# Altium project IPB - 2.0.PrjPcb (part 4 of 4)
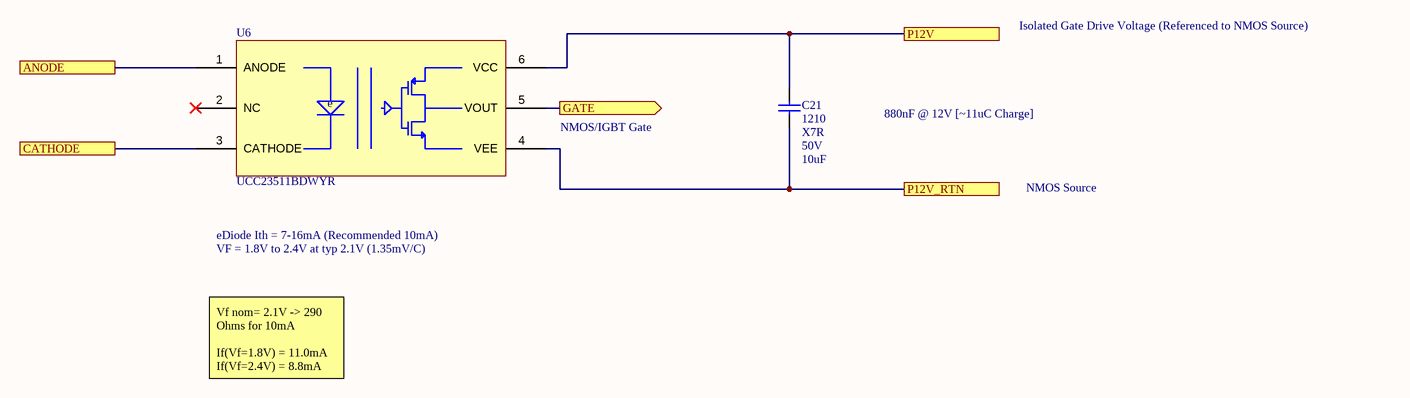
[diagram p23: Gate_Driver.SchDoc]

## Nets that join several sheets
COIL_DRV_HIGH: Local_Power_Supplies (Q1.2), 24V_to_12V_DCDC (C55.2 L4.1 R85.2), 24V_to_5V_DCDC (C45.2 L2.1 R81.2), Designator/Interface Channel A (K1_A.2 K2_A.2), Designator/Interface Channel A/Contactor Driver (D4_A.1), Designator/Interface Channel A/Contactor Driver (D4_B.1), Designator/Interface Channel A/Solid State Switches/Isolated Gate Drive Power - HIGH (C16_A.1 C17_A.2 C18_A.2 PS1_A.2), Designator/Interface Channel B (K1_B.2 K2_B.2), Designator/Interface Channel B/Contactor Driver (D4_C.1), Designator/Interface Channel B/Contactor Driver (D4_D.1), Designator/Interface Channel B/Solid State Switches/Isolated Gate Drive Power - HIGH (C16_B.1 C17_B.2 C18_B.2 PS1_B.2), Designator/Interface Channel C (K1_C.2 K2_C.2), Designator/Interface Channel C/Contactor Driver (D4_E.1), Designator/Interface Channel C/Contactor Driver (D4_F.1), Designator/Interface Channel C/Solid State Switches/Isolated Gate Drive Power - HIGH (C16_C.1 C17_C.2 C18_C.2 PS1_C.2), Designator/Interface Channel D (K1_D.2 K2_D.2), Designator/Interface Channel D/Contactor Driver (D4_G.1), Designator/Interface Channel D/Contactor Driver (D4_H.1), Designator/Interface Channel D/Solid State Switches/Isolated Gate Drive Power - HIGH (C16_D.1 C17_D.2 C18_D.2 PS1_D.2)
HV_P5V: Designator/Interface Channel A/Solid State Switches (C61_A.2 U22_A.5), Designator/Interface Channel A/Solid State Switches/Isolated Gate Drive Power - HIGH (C47_A.2 U15_A.3), Designator/Interface Channel A/Solid State Switches/Short Circuit Current Sense (5 pins), Designator/Interface Channel A/Solid State Switches/Short Circuit Logic Intergration (C51_A.2 Q5_A.2 U21_A.5)
HV_P5V: Designator/Interface Channel B/Solid State Switches (C61_B.2 U22_B.5), Designator/Interface Channel B/Solid State Switches/Isolated Gate Drive Power - HIGH (C47_B.2 U15_B.3), Designator/Interface Channel B/Solid State Switches/Short Circuit Current Sense (5 pins), Designator/Interface Channel B/Solid State Switches/Short Circuit Logic Intergration (C51_B.2 Q5_B.2 U21_B.5)
HV_P5V: Designator/Interface Channel C/Solid State Switches (C61_C.2 U22_C.5), Designator/Interface Channel C/Solid State Switches/Isolated Gate Drive Power - HIGH (C47_C.2 U15_C.3), Designator/Interface Channel C/Solid State Switches/Short Circuit Current Sense (5 pins), Designator/Interface Channel C/Solid State Switches/Short Circuit Logic Intergration (C51_C.2 Q5_C.2 U21_C.5)
HV_P5V: Designator/Interface Channel D/Solid State Switches (C61_D.2 U22_D.5), Designator/Interface Channel D/Solid State Switches/Isolated Gate Drive Power - HIGH (C47_D.2 U15_D.3), Designator/Interface Channel D/Solid State Switches/Short Circuit Current Sense (5 pins), Designator/Interface Channel D/Solid State Switches/Short Circuit Logic Intergration (C51_D.2 Q5_D.2 U21_D.5)
HV_P12V: Designator/Interface Channel A/Solid State Switches/Isolated Gate Drive Power - HIGH (6 pins), Designator/Interface Channel A/Solid State Switches/Short Circuit Logic Intergration/MOSFET HIGH Driver (C21_A.2 U6_A.6)
HV_P12V: Designator/Interface Channel B/Solid State Switches/Isolated Gate Drive Power - HIGH (6 pins), Designator/Interface Channel B/Solid State Switches/Short Circuit Logic Intergration/MOSFET HIGH Driver (C21_B.2 U6_B.6)
HV_P12V: Designator/Interface Channel C/Solid State Switches/Isolated Gate Drive Power - HIGH (6 pins), Designator/Interface Channel C/Solid State Switches/Short Circuit Logic Intergration/MOSFET HIGH Driver (C21_C.2 U6_C.6)
HV_P12V: Designator/Interface Channel D/Solid State Switches/Isolated Gate Drive Power - HIGH (6 pins), Designator/Interface Channel D/Solid State Switches/Short Circuit Logic Intergration/MOSFET HIGH Driver (C21_D.2 U6_D.6)
ISO_RTN_Solid State Switches: Designator/Interface Channel A/Solid State Switches (8 pins), Designator/Interface Channel A/Solid State Switches/Isolated Gate Drive Power - HIGH (8 pins), Designator/Interface Channel A/Solid State Switches/Short Circuit Current Sense (8 pins), Designator/Interface Channel A/Solid State Switches/Short Circuit Logic Intergration (5 pins), Designator/Interface Channel A/Solid State Switches/Short Circuit Logic Intergration/MOSFET HIGH Driver (C21_A.1 U6_A.3 U6_A.4)
ISO_RTN_Solid State Switches: Designator/Interface Channel B/Solid State Switches (8 pins), Designator/Interface Channel B/Solid State Switches/Isolated Gate Drive Power - HIGH (8 pins), Designator/Interface Channel B/Solid State Switches/Short Circuit Current Sense (8 pins), Designator/Interface Channel B/Solid State Switches/Short Circuit Logic Intergration (5 pins), Designator/Interface Channel B/Solid State Switches/Short Circuit Logic Intergration/MOSFET HIGH Driver (C21_B.1 U6_B.3 U6_B.4)
ISO_RTN_Solid State Switches: Designator/Interface Channel C/Solid State Switches (8 pins), Designator/Interface Channel C/Solid State Switches/Isolated Gate Drive Power - HIGH (8 pins), Designator/Interface Channel C/Solid State Switches/Short Circuit Current Sense (8 pins), Designator/Interface Channel C/Solid State Switches/Short Circuit Logic Intergration (5 pins), Designator/Interface Channel C/Solid State Switches/Short Circuit Logic Intergration/MOSFET HIGH Driver (C21_C.1 U6_C.3 U6_C.4)
ISO_RTN_Solid State Switches: Designator/Interface Channel D/Solid State Switches (8 pins), Designator/Interface Channel D/Solid State Switches/Isolated Gate Drive Power - HIGH (8 pins), Designator/Interface Channel D/Solid State Switches/Short Circuit Current Sense (8 pins), Designator/Interface Channel D/Solid State Switches/Short Circuit Logic Intergration (5 pins), Designator/Interface Channel D/Solid State Switches/Short Circuit Logic Intergration/MOSFET HIGH Driver (C21_D.1 U6_D.3 U6_D.4)
LV_GND: Top (5 pins), Input_Current_Limit (8 pins), Input Current Limit/Current Sense (C10_A.2 U4_A.5 U4_A.6), Input Current Limit/Current Limit - Configurable (8 pins), Input Current Limit/12V to 5V (Linear) - ISNS Power (C57_A.1 C58_A.1 R88_A.1 U20_A.4), Input Current Limit/Channel Logic (18 pins), Mezzanine_Conn (33 pins), Fault_Sensing (C11.2 C12.1 U5.7 U5.8), Local_Power_Supplies (C14.2 C15.2 R60.1), 24V_to_12V_DCDC (6 pins), 24V_to_5V_DCDC (6 pins), Designator/Interface Channel A (7 pins), Designator/Interface Channel A/Overcurrent Current Sense (C10_B.2 U4_B.5 U4_B.6), Designator/Interface Channel A/Channel Logic (18 pins), Designator/Interface Channel A/Current Limit - Configurable (8 pins), Designator/Interface Channel A/Contactor Driver (Q2_A.3 R65_A.1), Designator/Interface Channel A/Contactor Driver (Q2_B.3 R65_B.1), Designator/Interface Channel A/Anti-Alias Filter (5 pins), Designator/Interface Channel A/12V to 5V (Linear) - ISNS Power (C57_B.1 C58_B.1 R88_B.1 U20_B.4), Designator/Interface Channel A/Solid State Switches (Q4_A.2 Q8_A.3), Designator/Interface Channel A/Solid State Switches/Isolated Gate Drive Power - HIGH (C17_A.1 C18_A.1 C20_A.1 PS1_A.1), Designator/Interface Channel B (7 pins), Designator/Interface Channel B/Overcurrent Current Sense (C10_C.2 U4_C.5 U4_C.6), Designator/Interface Channel B/Channel Logic (18 pins), Designator/Interface Channel B/Current Limit - Configurable (8 pins), Designator/Interface Channel B/Contactor Driver (Q2_C.3 R65_C.1), Designator/Interface Channel B/Contactor Driver (Q2_D.3 R65_D.1), Designator/Interface Channel B/Anti-Alias Filter (5 pins), Designator/Interface Channel B/12V to 5V (Linear) - ISNS Power (C57_C.1 C58_C.1 R88_C.1 U20_C.4), Designator/Interface Channel B/Solid State Switches (Q4_B.2 Q8_B.3), Designator/Interface Channel B/Solid State Switches/Isolated Gate Drive Power - HIGH (C17_B.1 C18_B.1 C20_B.1 PS1_B.1), Designator/Interface Channel C (7 pins), Designator/Interface Channel C/Overcurrent Current Sense (C10_D.2 U4_D.5 U4_D.6), Designator/Interface Channel C/Channel Logic (18 pins), Designator/Interface Channel C/Current Limit - Configurable (8 pins), Designator/Interface Channel C/Contactor Driver (Q2_E.3 R65_E.1), Designator/Interface Channel C/Contactor Driver (Q2_F.3 R65_F.1), Designator/Interface Channel C/Anti-Alias Filter (5 pins), Designator/Interface Channel C/12V to 5V (Linear) - ISNS Power (C57_D.1 C58_D.1 R88_D.1 U20_D.4), Designator/Interface Channel C/Solid State Switches (Q4_C.2 Q8_C.3), Designator/Interface Channel C/Solid State Switches/Isolated Gate Drive Power - HIGH (C17_C.1 C18_C.1 C20_C.1 PS1_C.1), Designator/Interface Channel D (7 pins), Designator/Interface Channel D/Overcurrent Current Sense (C10_E.2 U4_E.5 U4_E.6), Designator/Interface Channel D/Channel Logic (18 pins), Designator/Interface Channel D/Current Limit - Configurable (8 pins), Designator/Interface Channel D/Contactor Driver (Q2_G.3 R65_G.1), Designator/Interface Channel D/Contactor Driver (Q2_H.3 R65_H.1), Designator/Interface Channel D/Anti-Alias Filter (5 pins), Designator/Interface Channel D/12V to 5V (Linear) - ISNS Power (C57_E.1 C58_E.1 R88_E.1 U20_E.4), Designator/Interface Channel D/Solid State Switches (Q4_D.2 Q8_D.3), Designator/Interface Channel D/Solid State Switches/Isolated Gate Drive Power - HIGH (C17_D.1 C18_D.1 C20_D.1 PS1_D.1)
LV_IGB_P24V: Mezzanine_Conn (5 pins), Local_Power_Supplies (D2.1)
LV_ISNS_P5V: Input_Current_Limit (5 pins), Input Current Limit/Current Sense (C10_A.1 U4_A.8), Input Current Limit/12V to 5V (Linear) - ISNS Power (C58_A.2 R87_A.2 U20_A.6)
LV_ISNS_P12V: Input Current Limit/12V to 5V (Linear) - ISNS Power (C57_A.2 U20_A.2), Local_Power_Supplies (C14.1 L1.2 R59.2), Designator/Interface Channel A/12V to 5V (Linear) - ISNS Power (C57_B.2 U20_B.2), Designator/Interface Channel B/12V to 5V (Linear) - ISNS Power (C57_C.2 U20_C.2), Designator/Interface Channel C/12V to 5V (Linear) - ISNS Power (C57_D.2 U20_D.2), Designator/Interface Channel D/12V to 5V (Linear) - ISNS Power (C57_E.2 U20_E.2)
LV_P5V: Top (U1.2), Input_Current_Limit (R42.2), Input Current Limit/Current Limit - Configurable (5 pins), Input Current Limit/Channel Logic (15 pins), Fault_Sensing (C11.1 C12.2 U5.16), 24V_to_5V_DCDC (C42.1 U17.3), Designator/Interface Channel A (5 pins), Designator/Interface Channel A/Channel Logic (15 pins), Designator/Interface Channel A/Current Limit - Configurable (5 pins), Designator/Interface Channel A/Anti-Alias Filter (C36_A.1 C37_A.2 U16_A.8), Designator/Interface Channel B (5 pins), Designator/Interface Channel B/Channel Logic (15 pins), Designator/Interface Channel B/Current Limit - Configurable (5 pins), Designator/Interface Channel B/Anti-Alias Filter (C36_B.1 C37_B.2 U16_B.8), Designator/Interface Channel C (5 pins), Designator/Interface Channel C/Channel Logic (15 pins), Designator/Interface Channel C/Current Limit - Configurable (5 pins), Designator/Interface Channel C/Anti-Alias Filter (C36_C.1 C37_C.2 U16_C.8), Designator/Interface Channel D (5 pins), Designator/Interface Channel D/Channel Logic (15 pins), Designator/Interface Channel D/Current Limit - Configurable (5 pins), Designator/Interface Channel D/Anti-Alias Filter (C36_D.1 C37_D.2 U16_D.8)
LV_P12V: Local_Power_Supplies (L1.1), 24V_to_12V_DCDC (C52.1 U19.3)
N187: IGB_Power_Conn (J1.B), Designator/Interface Channel A (K2_A.1 R103_A.1), Designator/Interface Channel B (K2_B.1 R103_B.1), Designator/Interface Channel C (K2_C.1 R103_C.1), Designator/Interface Channel D (K2_D.1 R103_D.1)
ACTIVE-FAULT: Input_Current_Limit (R41.1 TP1.1), Input Current Limit/Channel Logic (R71_A.2 U11_A.1)
ACTIVE-FAULT: Designator/Interface Channel A/Channel Logic (R71_B.2 U11_B.1), Designator/Interface Channel A/Current Limit - Configurable (U8_B.4)
ACTIVE-FAULT: Designator/Interface Channel B/Channel Logic (R71_C.2 U11_C.1), Designator/Interface Channel B/Current Limit - Configurable (U8_C.4)
ACTIVE-FAULT: Designator/Interface Channel C/Channel Logic (R71_D.2 U11_D.1), Designator/Interface Channel C/Current Limit - Configurable (U8_D.4)
ACTIVE-FAULT: Designator/Interface Channel D/Channel Logic (R71_E.2 U11_E.1), Designator/Interface Channel D/Current Limit - Configurable (U8_E.4)
BOARD_TEMP: Top (C1.2 R1.1), Mezzanine_Conn (R33.1 R36.1)
CH-EN_Solid State Switches: Designator/Interface Channel A/Solid State Switches (Q4_A.4), Designator/Interface Channel A/Solid State Switches/Short Circuit Logic Intergration (R92_A.1)
CH-EN_Solid State Switches: Designator/Interface Channel B/Solid State Switches (Q4_B.4), Designator/Interface Channel B/Solid State Switches/Short Circuit Logic Intergration (R92_B.1)
CH-EN_Solid State Switches: Designator/Interface Channel C/Solid State Switches (Q4_C.4), Designator/Interface Channel C/Solid State Switches/Short Circuit Logic Intergration (R92_C.1)
CH-EN_Solid State Switches: Designator/Interface Channel D/Solid State Switches (Q4_D.4), Designator/Interface Channel D/Solid State Switches/Short Circuit Logic Intergration (R92_D.1)
CH-ENABLE: Input_Current_Limit (C2.2 R42.1), Input Current Limit/Channel Logic (R73_A.2 U10_A.3)
CH-I_Interface Channel A: Designator/Interface Channel A/Overcurrent Current Sense (U4_B.7), Designator/Interface Channel A/Current Limit - Configurable (R69_B.1), Designator/Interface Channel A/Anti-Alias Filter (R79_A.1)
CH-I_Interface Channel B: Designator/Interface Channel B/Overcurrent Current Sense (U4_C.7), Designator/Interface Channel B/Current Limit - Configurable (R69_C.1), Designator/Interface Channel B/Anti-Alias Filter (R79_B.1)
CH-I_Interface Channel C: Designator/Interface Channel C/Overcurrent Current Sense (U4_D.7), Designator/Interface Channel C/Current Limit - Configurable (R69_D.1), Designator/Interface Channel C/Anti-Alias Filter (R79_C.1)
CH-I_Interface Channel D: Designator/Interface Channel D/Overcurrent Current Sense (U4_E.7), Designator/Interface Channel D/Current Limit - Configurable (R69_E.1), Designator/Interface Channel D/Anti-Alias Filter (R79_D.1)
CHA_CURRENT_SET: Mezzanine_Conn (R4.1 R6.1), Designator/Interface Channel A/Current Limit - Configurable (R66_B.1)
CHA_FET_EN: Mezzanine_Conn (R19.1 R21.1), Designator/Interface Channel A/Channel Logic (R73_B.2 U10_B.3)
CHA_I: Mezzanine_Conn (R20.1 R22.1), Designator/Interface Channel A/Anti-Alias Filter (C38_A.1 U16_A.6 U16_A.7)
CHA_RLY_EN: Mezzanine_Conn (R3.1 R5.1), Designator/Interface Channel A/Contactor Driver (R64_A.1), Designator/Interface Channel A/Contactor Driver (R64_B.1)
CHB_CURRENT_SET: Mezzanine_Conn (R8.1 R10.1), Designator/Interface Channel B/Current Limit - Configurable (R66_C.1)
CHB_FET_EN: Mezzanine_Conn (R23.1 R25.1), Designator/Interface Channel B/Channel Logic (R73_C.2 U10_C.3)
CHB_I: Mezzanine_Conn (R24.1 R26.1), Designator/Interface Channel B/Anti-Alias Filter (C38_B.1 U16_B.6 U16_B.7)
CHB_RLY_EN: Mezzanine_Conn (R7.1 R9.1), Designator/Interface Channel B/Contactor Driver (R64_C.1), Designator/Interface Channel B/Contactor Driver (R64_D.1)
CHC_CURRENT_SET: Mezzanine_Conn (R12.1 R14.1), Designator/Interface Channel C/Current Limit - Configurable (R66_D.1)
CHC_FET_EN: Mezzanine_Conn (R27.1 R29.1), Designator/Interface Channel C/Channel Logic (R73_D.2 U10_D.3)
CHC_I: Mezzanine_Conn (R28.1 R30.1), Designator/Interface Channel C/Anti-Alias Filter (C38_C.1 U16_C.6 U16_C.7)
CHC_RLY_EN: Mezzanine_Conn (R11.1 R13.1), Designator/Interface Channel C/Contactor Driver (R64_E.1), Designator/Interface Channel C/Contactor Driver (R64_F.1)
CHD_CURRENT_SET: Mezzanine_Conn (R16.1 R18.1), Designator/Interface Channel D/Current Limit - Configurable (R66_E.1)
CHD_FET_EN: Mezzanine_Conn (R31.1 R34.1), Designator/Interface Channel D/Channel Logic (R73_E.2 U10_E.3)
CHD_I: Mezzanine_Conn (R32.1 R35.1), Designator/Interface Channel D/Anti-Alias Filter (C38_D.1 U16_D.6 U16_D.7)
CHD_RLY_EN: Mezzanine_Conn (R15.1 R17.1), Designator/Interface Channel D/Contactor Driver (R64_G.1), Designator/Interface Channel D/Contactor Driver (R64_H.1)
COIL_RTN_HIGH_Interface Channel A: Designator/Interface Channel A (K1_A.5), Designator/Interface Channel A/Contactor Driver (D4_A.2 Q2_A.2)
COIL_RTN_HIGH_Interface Channel B: Designator/Interface Channel B (K1_B.5), Designator/Interface Channel B/Contactor Driver (D4_C.2 Q2_C.2)
COIL_RTN_HIGH_Interface Channel C: Designator/Interface Channel C (K1_C.5), Designator/Interface Channel C/Contactor Driver (D4_E.2 Q2_E.2)
COIL_RTN_HIGH_Interface Channel D: Designator/Interface Channel D (K1_D.5), Designator/Interface Channel D/Contactor Driver (D4_G.2 Q2_G.2)
COIL_RTN_LOW_Interface Channel A: Designator/Interface Channel A (K2_A.5), Designator/Interface Channel A/Contactor Driver (D4_B.2 Q2_B.2)
COIL_RTN_LOW_Interface Channel B: Designator/Interface Channel B (K2_B.5), Designator/Interface Channel B/Contactor Driver (D4_D.2 Q2_D.2)
COIL_RTN_LOW_Interface Channel C: Designator/Interface Channel C (K2_C.5), Designator/Interface Channel C/Contactor Driver (D4_F.2 Q2_F.2)
COIL_RTN_LOW_Interface Channel D: Designator/Interface Channel D (K2_D.5), Designator/Interface Channel D/Contactor Driver (D4_H.2 Q2_H.2)
FAULT-BUF_Solid State Switches: Designator/Interface Channel A/Solid State Switches (R83_A.2 TP5_A.1 U22_A.4), Designator/Interface Channel A/Solid State Switches/Short Circuit Logic Intergration (Q6_A.1 R90_A.2)
FAULT-BUF_Solid State Switches: Designator/Interface Channel B/Solid State Switches (R83_B.2 TP5_B.1 U22_B.4), Designator/Interface Channel B/Solid State Switches/Short Circuit Logic Intergration (Q6_B.1 R90_B.2)
FAULT-BUF_Solid State Switches: Designator/Interface Channel C/Solid State Switches (R83_C.2 TP5_C.1 U22_C.4), Designator/Interface Channel C/Solid State Switches/Short Circuit Logic Intergration (Q6_C.1 R90_C.2)
FAULT-BUF_Solid State Switches: Designator/Interface Channel D/Solid State Switches (R83_D.2 TP5_D.1 U22_D.4), Designator/Interface Channel D/Solid State Switches/Short Circuit Logic Intergration (Q6_D.1 R90_D.2)
FAULT-INJECT_Interface Channel A: Designator/Interface Channel A/Current Limit - Configurable (C24_B.1 R66_B.2 U7_B.2), Designator/Interface Channel A/Solid State Switches (Q8_A.4)
FAULT-INJECT_Interface Channel B: Designator/Interface Channel B/Current Limit - Configurable (C24_C.1 R66_C.2 U7_C.2), Designator/Interface Channel B/Solid State Switches (Q8_B.4)
FAULT-INJECT_Interface Channel C: Designator/Interface Channel C/Current Limit - Configurable (C24_D.1 R66_D.2 U7_D.2), Designator/Interface Channel C/Solid State Switches (Q8_C.4)
FAULT-INJECT_Interface Channel D: Designator/Interface Channel D/Current Limit - Configurable (C24_E.1 R66_E.2 U7_E.2), Designator/Interface Channel D/Solid State Switches (Q8_D.4)
FAULT_MUX_A: Mezzanine_Conn (J3.58), Fault_Sensing (U5.11)
FAULT_MUX_B: Mezzanine_Conn (J3.60), Fault_Sensing (U5.10)
FAULT_MUX_C: Mezzanine_Conn (J3.62), Fault_Sensing (U5.9)
FAULT_SENSE: Mezzanine_Conn (R39.1 R40.1), Fault_Sensing (U5.5)
FAULT_SENSE_IN0: Input Current Limit/Channel Logic (U11_A.4 U12_A.1 U14_A.6), Fault_Sensing (U5.4), Designator/Interface Channel A/Channel Logic (R70_B.2 U9_B.3), Designator/Interface Channel B/Channel Logic (R70_C.2 U9_C.3), Designator/Interface Channel C/Channel Logic (R70_D.2 U9_D.3), Designator/Interface Channel D/Channel Logic (R70_E.2 U9_E.3)
FAULT_SENSE_IN1: Fault_Sensing (U5.3), Designator/Interface Channel A/Channel Logic (U11_B.4 U12_B.1 U14_B.6)
FAULT_SENSE_IN2: Fault_Sensing (U5.2), Designator/Interface Channel B/Channel Logic (U11_C.4 U12_C.1 U14_C.6)
FAULT_SENSE_IN3: Fault_Sensing (U5.1), Designator/Interface Channel C/Channel Logic (U11_D.4 U12_D.1 U14_D.6)
FAULT_SENSE_IN4: Fault_Sensing (U5.15), Designator/Interface Channel D/Channel Logic (U11_E.4 U12_E.1 U14_E.6)
FAULT_SENSE_IN5: Top (R97.2), Fault_Sensing (U5.14)
FAULT_SENSE_IN6: Top (R96.2), Fault_Sensing (U5.13)
FAULT_SENSE_IN7: Top (R95.2), Fault_Sensing (U5.12)
GATE_DRV_HIGH_Solid State Switches: Designator/Interface Channel A/Solid State Switches (D7_A.2 R91_A.1), Designator/Interface Channel A/Solid State Switches/Short Circuit Logic Intergration/MOSFET HIGH Driver (U6_A.5)
GATE_DRV_HIGH_Solid State Switches: Designator/Interface Channel B/Solid State Switches (D7_B.2 R91_B.1), Designator/Interface Channel B/Solid State Switches/Short Circuit Logic Intergration/MOSFET HIGH Driver (U6_B.5)
GATE_DRV_HIGH_Solid State Switches: Designator/Interface Channel C/Solid State Switches (D7_C.2 R91_C.1), Designator/Interface Channel C/Solid State Switches/Short Circuit Logic Intergration/MOSFET HIGH Driver (U6_C.5)
GATE_DRV_HIGH_Solid State Switches: Designator/Interface Channel D/Solid State Switches (D7_D.2 R91_D.1), Designator/Interface Channel D/Solid State Switches/Short Circuit Logic Intergration/MOSFET HIGH Driver (U6_D.5)
INPUT-FAULT-RESET: Input Current Limit/Channel Logic (R74_A.2 U14_A.1), Mezzanine_Conn (R37.1 R38.1)
NetC10_B_1: Designator/Interface Channel A/Overcurrent Current Sense (C10_B.1 U4_B.8), Designator/Interface Channel A/12V to 5V (Linear) - ISNS Power (C58_B.2 R87_B.2 U20_B.6)
NetC10_C_1: Designator/Interface Channel B/Overcurrent Current Sense (C10_C.1 U4_C.8), Designator/Interface Channel B/12V to 5V (Linear) - ISNS Power (C58_C.2 R87_C.2 U20_C.6)
NetC10_D_1: Designator/Interface Channel C/Overcurrent Current Sense (C10_D.1 U4_D.8), Designator/Interface Channel C/12V to 5V (Linear) - ISNS Power (C58_D.2 R87_D.2 U20_D.6)
NetC10_E_1: Designator/Interface Channel D/Overcurrent Current Sense (C10_E.1 U4_E.8), Designator/Interface Channel D/12V to 5V (Linear) - ISNS Power (C58_E.2 R87_E.2 U20_E.6)
NetC59_A_1: Designator/Interface Channel A/Overcurrent Current Sense (U4_B.3 U4_B.4), Designator/Interface Channel A/Solid State Switches (C59_A.1 Q3_A.D)
NetC59_B_1: Designator/Interface Channel B/Overcurrent Current Sense (U4_C.3 U4_C.4), Designator/Interface Channel B/Solid State Switches (C59_B.1 Q3_B.D)
NetC59_C_1: Designator/Interface Channel C/Overcurrent Current Sense (U4_D.3 U4_D.4), Designator/Interface Channel C/Solid State Switches (C59_C.1 Q3_C.D)
NetC59_D_1: Designator/Interface Channel D/Overcurrent Current Sense (U4_E.3 U4_E.4), Designator/Interface Channel D/Solid State Switches (C59_D.1 Q3_D.D)
NetD1_A_1: External_Interface_Conn (J4.B), Designator/Interface Channel A (D1_A.1 D1_A.3 K2_A.3)
NetD1_A_4: External_Interface_Conn (J4.A), Designator/Interface Channel A (D1_A.4 K1_A.3)
NetD1_B_1: External_Interface_Conn (J5.B), Designator/Interface Channel B (D1_B.1 D1_B.3 K2_B.3)
NetD1_B_4: External_Interface_Conn (J5.A), Designator/Interface Channel B (D1_B.4 K1_B.3)
NetD1_C_1: External_Interface_Conn (J6.B), Designator/Interface Channel C (D1_C.1 D1_C.3 K2_C.3)
NetD1_C_4: External_Interface_Conn (J6.A), Designator/Interface Channel C (D1_C.4 K1_C.3)
NetD1_D_1: External_Interface_Conn (J7.B), Designator/Interface Channel D (D1_D.1 D1_D.3 K2_D.3)
NetD1_D_4: External_Interface_Conn (J7.A), Designator/Interface Channel D (D1_D.4 K1_D.3)
NetD8_A_2: Designator/Interface Channel A (K1_A.1 R99_A.1), Designator/Interface Channel A/Solid State Switches/Short Circuit Current Sense (D8_A.2 R102_A.2 U18_A.7)
NetD8_B_2: Designator/Interface Channel B (K1_B.1 R99_B.1), Designator/Interface Channel B/Solid State Switches/Short Circuit Current Sense (D8_B.2 R102_B.2 U18_B.7)
NetD8_C_2: Designator/Interface Channel C (K1_C.1 R99_C.1), Designator/Interface Channel C/Solid State Switches/Short Circuit Current Sense (D8_C.2 R102_C.2 U18_C.7)
NetD8_D_2: Designator/Interface Channel D (K1_D.1 R99_D.1), Designator/Interface Channel D/Solid State Switches/Short Circuit Current Sense (D8_D.2 R102_D.2 U18_D.7)
NetQ6_A_3: Designator/Interface Channel A/Solid State Switches/Short Circuit Logic Intergration (Q6_A.3 R76_A.2), Designator/Interface Channel A/Solid State Switches/Short Circuit Logic Intergration/MOSFET HIGH Driver (U6_A.1)
NetQ6_B_3: Designator/Interface Channel B/Solid State Switches/Short Circuit Logic Intergration (Q6_B.3 R76_B.2), Designator/Interface Channel B/Solid State Switches/Short Circuit Logic Intergration/MOSFET HIGH Driver (U6_B.1)
NetQ6_C_3: Designator/Interface Channel C/Solid State Switches/Short Circuit Logic Intergration (Q6_C.3 R76_C.2), Designator/Interface Channel C/Solid State Switches/Short Circuit Logic Intergration/MOSFET HIGH Driver (U6_C.1)
NetQ6_D_3: Designator/Interface Channel D/Solid State Switches/Short Circuit Logic Intergration (Q6_D.3 R76_D.2), Designator/Interface Channel D/Solid State Switches/Short Circuit Logic Intergration/MOSFET HIGH Driver (U6_D.1)
NetR41_2: Input_Current_Limit (R41.2), Input Current Limit/Current Limit - Configurable (U8_A.4)
NetR63_A_1: Designator/Interface Channel A/Channel Logic (U12_B.3 U13_B.4), Designator/Interface Channel A/Solid State Switches (R63_A.1)
NetR63_B_1: Designator/Interface Channel B/Channel Logic (U12_C.3 U13_C.4), Designator/Interface Channel B/Solid State Switches (R63_B.1)
NetR63_C_1: Designator/Interface Channel C/Channel Logic (U12_D.3 U13_D.4), Designator/Interface Channel C/Solid State Switches (R63_C.1)
NetR63_D_1: Designator/Interface Channel D/Channel Logic (U12_E.3 U13_E.4), Designator/Interface Channel D/Solid State Switches (R63_D.1)
NetR69_A_1: Input Current Limit/Current Sense (U4_A.7), Input Current Limit/Current Limit - Configurable (R69_A.1)
NetR93_A_1: Designator/Interface Channel A/Solid State Switches (U22_A.2), Designator/Interface Channel A/Solid State Switches/Short Circuit Current Sense (R93_A.1 U18_A.6)
NetR93_B_1: Designator/Interface Channel B/Solid State Switches (U22_B.2), Designator/Interface Channel B/Solid State Switches/Short Circuit Current Sense (R93_B.1 U18_B.6)
NetR93_C_1: Designator/Interface Channel C/Solid State Switches (U22_C.2), Designator/Interface Channel C/Solid State Switches/Short Circuit Current Sense (R93_C.1 U18_C.6)
NetR93_D_1: Designator/Interface Channel D/Solid State Switches (U22_D.2), Designator/Interface Channel D/Solid State Switches/Short Circuit Current Sense (R93_D.1 U18_D.6)
NetU4_A_3: Input Current Limit/Current Sense (U4_A.3 U4_A.4), Designator/Interface Channel A/Overcurrent Current Sense (U4_B.1 U4_B.2), Designator/Interface Channel B/Overcurrent Current Sense (U4_C.1 U4_C.2), Designator/Interface Channel C/Overcurrent Current Sense (U4_D.1 U4_D.2), Designator/Interface Channel D/Overcurrent Current Sense (U4_E.1 U4_E.2)
P187: IGB_Power_Conn (J1.A), Input Current Limit/Current Sense (U4_A.1 U4_A.2)
RESETn_Solid State Switches: Designator/Interface Channel A/Solid State Switches/Short Circuit Current Sense (C48_A.2 R62_A.1 U18_A.5), Designator/Interface Channel A/Solid State Switches/Short Circuit Logic Intergration (U21_A.4)
RESETn_Solid State Switches: Designator/Interface Channel B/Solid State Switches/Short Circuit Current Sense (C48_B.2 R62_B.1 U18_B.5), Designator/Interface Channel B/Solid State Switches/Short Circuit Logic Intergration (U21_B.4)
RESETn_Solid State Switches: Designator/Interface Channel C/Solid State Switches/Short Circuit Current Sense (C48_C.2 R62_C.1 U18_C.5), Designator/Interface Channel C/Solid State Switches/Short Circuit Logic Intergration (U21_C.4)
RESETn_Solid State Switches: Designator/Interface Channel D/Solid State Switches/Short Circuit Current Sense (C48_D.2 R62_D.1 U18_D.5), Designator/Interface Channel D/Solid State Switches/Short Circuit Logic Intergration (U21_D.4)
V_DELAY: Input_Current_Limit (R49.1 TP3.1), Input Current Limit/Current Limit - Configurable (U7_A.6)
V_DELAY_Interface Channel A: Designator/Interface Channel A (R53_A.1 TP4_A.1), Designator/Interface Channel A/Current Limit - Configurable (U7_B.6)
V_DELAY_Interface Channel B: Designator/Interface Channel B (R53_B.1 TP4_B.1), Designator/Interface Channel B/Current Limit - Configurable (U7_C.6)
V_DELAY_Interface Channel C: Designator/Interface Channel C (R53_C.1 TP4_C.1), Designator/Interface Channel C/Current Limit - Configurable (U7_D.6)
V_DELAY_Interface Channel D: Designator/Interface Channel D (R53_D.1 TP4_D.1), Designator/Interface Channel D/Current Limit - Configurable (U7_E.6)
V_ISET: Input_Current_Limit (R45.1 TP2.1), Input Current Limit/Current Limit - Configurable (R66_A.1)

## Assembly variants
MAIN: not fitted C16_A C16_B C16_C C16_D R5 R6 R9 R10 R13 R14 R17 R18 R21 R22 R25 R26 R29 R30 R34 R35 R36 R38 R40 R87_B R87_C R87_D R87_E R88_B R88_C R88_D R88_E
